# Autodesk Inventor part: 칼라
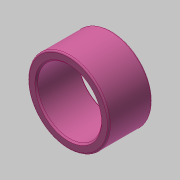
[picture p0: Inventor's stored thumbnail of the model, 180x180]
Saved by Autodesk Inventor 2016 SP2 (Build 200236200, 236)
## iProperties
Created: 2019-05
Part Number: 칼라
Material: 스테인리스강
Document SubType Name: Modeling
Designer: mduedu
Density: 1 g/cm^3
Appearance: 분홍색
Author: mduedu
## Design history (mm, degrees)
sketch "스케치1"
  geometry: C1 r 11 at (0, 0); C2 r 14 at (0, 0); 1 further point
  constraints: 2 centre point, 2 coincident
  dimensions: "d0" = 22 diameter of C1; "d1" = 28 diameter of C2
extrude "돌출1" new body sketch "스케치1" distance "d2" = 15; taper "d3" = 0 deg
fillet "모깎기1" dims "d4" = 0.5
chamfer "모따기1" distance "d5" = 0.5; stored, may be unused: second distance "d6" = 2, angle "d7" = 45 deg
node "솔리드1"
